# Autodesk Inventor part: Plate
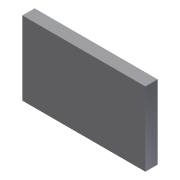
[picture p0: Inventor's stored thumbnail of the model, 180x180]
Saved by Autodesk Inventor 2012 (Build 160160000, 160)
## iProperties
Created: 2009-05
Part Number: Plate
Document SubType Name: Modeling
Designer: Sham
Density: 1 g/cm^3
Material: Default
Author: Sham
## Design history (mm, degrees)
sketch "Sketch1"
  geometry: L1 (12.538, -14.287)-(-37.462, -14.288); L2 (-37.462, -14.288)-(-37.463, 15.712); L3 (-37.463, 15.712)-(12.537, 15.713); L4 (12.537, 15.713)-(12.538, -14.287)
  constraints: 8 end point, 2 parallel, 1 horizontal, 1 perpendicular
  dimensions: "d0" = 50 distance of L1.start L1.end; "d1" = 30 distance of L3.end L1.start
extrude "Extrusion1" new body sketch "Sketch1" distance "d2" = 5; taper "d3" = 0 deg
body "Solid1"
